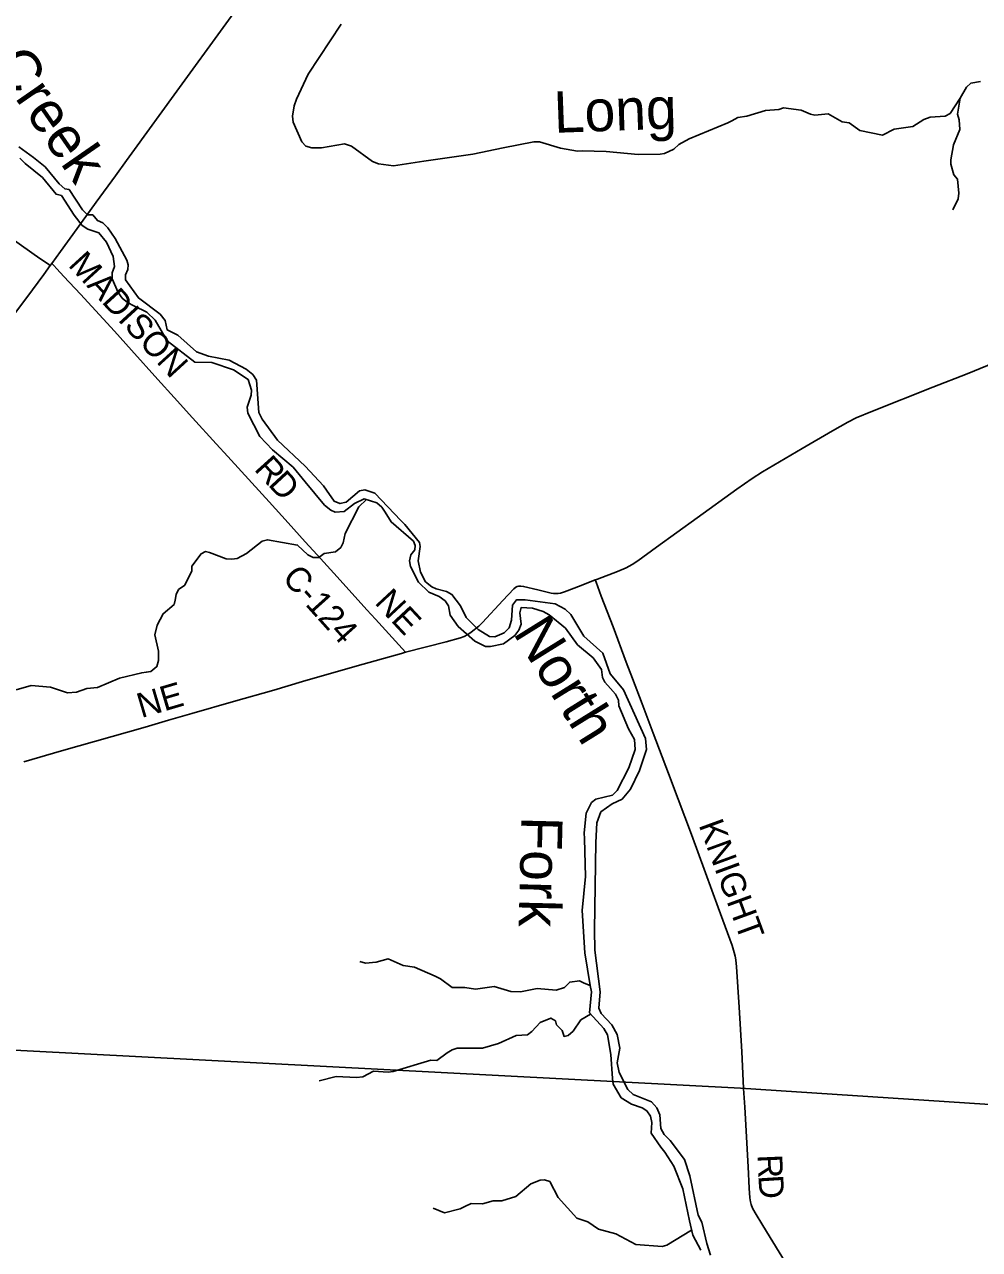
# Model space of a CAD drawing. Extents: x -51392 to 1635000, y 156707 to 696232.
# Drawn here: x 168915 to 180473, y 515913 to 530739 of the extents above; entities that cross this region are included whole.
import ezdxf

# ---------------------------------------------------------------- set-up
doc = ezdxf.new("R2010")
doc.units = 0
for name, color, linetype in [('GM_X_County_Road', 7, 'Continuous'), ('GM_X_County_Road_Text', 7, 'Continuous'), ('GM_X_Major_River', 7, 'Continuous'), ('GM_X_Major_River_Text', 7, 'Continuous'), ('GM_X_Minor_River', 7, 'Continuous'), ('GM_X_Minor_River_Text', 7, 'Continuous'), ('GM_X_Township', 7, 'Continuous'), ('GM_X_Township_Road', 7, 'Continuous'), ('GM_X_Township_Road_Text', 7, 'Continuous'), ('GM_X_US_Route', 7, 'Continuous')]:
    doc.layers.add(name, color=color, linetype=linetype)

msp = doc.modelspace()

# ---------------------------------------------------------------- linework, layer by layer
at = {"layer": 'GM_X_County_Road'}
for points in [[(167287, 529285), (167296, 529278), (167614, 529025), (167969, 528741), (168202, 528558), (168356, 528437), (168505, 528327), (168680, 528204), (168878, 528064), (169102, 527908), (169195, 527844), (169227, 527821)], [(173528, 523141), (173163, 523542), (173057, 523656), (172808, 523932), (172658, 524099), (172457, 524321), (172313, 524478), (172106, 524707), (171877, 524961), (171665, 525193), (171378, 525509), (171234, 525665), (170950, 525979), (170728, 526226), (170530, 526444), (170212, 526797), (170003, 527029), (169594, 527473), (169393, 527690), (169308, 527783), (169270, 527821), (169245, 527845)]]:
    msp.add_lwpolyline(points, dxfattribs=at)
at = {"layer": 'GM_X_Major_River'}
for points in [[(175686, 523337), (175528, 523598), (175458, 523662), (175337, 523726), (174976, 523777), (174868, 523775), (174820, 523711), (174810, 523530), (174782, 523438), (174719, 523376), (174607, 523328), (174541, 523330), (174406, 523416), (174262, 523560), (174194, 523703), (174088, 523841), (174024, 523877), (173897, 523910), (173845, 523932), (173769, 523994), (173707, 524110), (173679, 524247), (173705, 524419), (173695, 524469), (173519, 524686), (173470, 524736), (173156, 525067), (173033, 525106), (172971, 525094), (172807, 524959), (172733, 524941), (172662, 524969), (172570, 525102), (172536, 525156), (172314, 525393), (171979, 525708), (171790, 525963), (171752, 526043), (171724, 526434), (171678, 526502), (171600, 526569), (171392, 526675), (171141, 526723), (170997, 526778), (170770, 526978), (170644, 527043), (170618, 527157), (170556, 527231), (170295, 527430), (170139, 527647), (170137, 527709), (170165, 527773), (170169, 527829), (170155, 527885), (170012, 528150), (169924, 528277), (169862, 528337), (169798, 528365), (169742, 528435), (169678, 528435), (169618, 528495), (169455, 528740), (169405, 528748), (169337, 528810), (169165, 529015), (169026, 529129), (168848, 529260)], [(168858, 529120), (168924, 529055), (169134, 528885), (169297, 528684), (169363, 528670), (169515, 528431), (169613, 528307), (169680, 528261), (169754, 528238), (169816, 528216), (169906, 528106), (169990, 527929), (170004, 527809), (169976, 527735), (169976, 527661), (170048, 527496), (170096, 527428), (170161, 527374), (170237, 527332), (170397, 527257), (170497, 527159), (170644, 526912), (170978, 526653), (171183, 526647), (171444, 526561), (171624, 526442), (171664, 526314), (171660, 526252), (171612, 526107), (171620, 526033), (171762, 525754), (171917, 525592), (172167, 525381), (172311, 525204), (172548, 524923), (172622, 524861), (172676, 524837), (172785, 524845), (172909, 524943), (173025, 524999), (173178, 524951), (173240, 524895), (173280, 524837), (173352, 524718), (173625, 524485), (173645, 524431), (173641, 524381), (173589, 524319), (173575, 524249), (173587, 524177), (173683, 523988), (173809, 523868), (173935, 523817), (174006, 523763), (174048, 523701), (174068, 523591), (174164, 523452), (174366, 523277), (174495, 523211), (174555, 523209), (174711, 523241), (174848, 523343), (174900, 523410), (174926, 523482), (174910, 523620), (174928, 523684), (175062, 523674), (175193, 523634)], [(175193, 523634), (175267, 523592), (175461, 523431), (175610, 523229), (175796, 523072), (175898, 522932), (175912, 522837), (175940, 522777), (176009, 522701), (176069, 522633), (176103, 522562), (176109, 522492), (176227, 522213), (176297, 522087), (176307, 521965), (176229, 521742), (176088, 521467), (176030, 521413), (175830, 521361), (175779, 521321), (175713, 521193), (175687, 520954), (175691, 520882), (175705, 520426), (175666, 520017), (175698, 519504), (175760, 519106), (175777, 519031)], [(175883, 519032), (175817, 519536), (175813, 519780), (175831, 520837), (175843, 521078), (175890, 521209), (176028, 521307), (176148, 521363), (176251, 521483), (176357, 521708), (176377, 521772), (176442, 521962), (176432, 522097), (176163, 522687), (176107, 522755), (176005, 522879), (175915, 523128), (175686, 523337)], [(175777, 519031), (175754, 518776), (175927, 518586), (175971, 518511), (176011, 518273), (176031, 517982), (176041, 517912), (176137, 517750), (176261, 517672), (176389, 517627), (176447, 517589), (176493, 517525), (176507, 517451), (176501, 517321), (176617, 517152), (176665, 517092), (176775, 516922), (176883, 516645), (176964, 516260), (177002, 516086), (177102, 515905)], [(177218, 515845), (177174, 515987), (177111, 516243), (177070, 516329), (176967, 516805), (176901, 517002), (176731, 517230), (176657, 517304), (176617, 517377), (176605, 517543), (176567, 517629), (176503, 517699), (176281, 517788), (176219, 517850), (176111, 518056), (176089, 518173), (176121, 518351), (176087, 518513), (176025, 518632), (175894, 518768), (175866, 518834), (175883, 519032)]]:
    msp.add_lwpolyline(points, dxfattribs=at)
at = {"layer": 'GM_X_Minor_River'}
for points in [[(180238, 529848), (180117, 529663), (180059, 529631), (179877, 529619), (179798, 529589), (179668, 529503), (179439, 529471), (179299, 529401), (179026, 529457), (178896, 529548), (178812, 529562), (178643, 529658), (178479, 529642), (178429, 529654), (178316, 529702), (178100, 529731), (178046, 529709), (177883, 529697), (177656, 529629), (177548, 529613), (177476, 529573), (177426, 529548), (176960, 529356), (176834, 529286), (176774, 529228), (176661, 529176), (176607, 529170), (176343, 529166), (175953, 529202), (175665, 529210), (175609, 529206), (175404, 529241), (175147, 529317), (175079, 529317), (174708, 529245), (174341, 529171), (173747, 529085), (173382, 529029), (173200, 529051), (173128, 529081), (172871, 529268), (172787, 529294), (172510, 529246), (172392, 529244), (172319, 529266), (172271, 529320), (172167, 529555), (172159, 529631), (172181, 529756), (172207, 529834), (172348, 530137), (172747, 530741)], [(180484, 530050), (180368, 530028), (180314, 529982), (180238, 529848), (180207, 529653), (180229, 529583), (180237, 529467), (180157, 529284), (180125, 529100), (180125, 529047), (180163, 528921), (180207, 528867), (180225, 528696), (180213, 528630), (180151, 528496)], [(173055, 524990), (172963, 524899), (172795, 524578), (172772, 524466), (172742, 524408), (172678, 524358), (172544, 524338), (172478, 524289), (172409, 524289), (172345, 524320), (172221, 524438), (171858, 524502), (171792, 524484), (171603, 524338), (171491, 524276), (171425, 524268), (171356, 524270), (171156, 524350), (171106, 524360), (171052, 524334), (170941, 524182), (170939, 524126), (170855, 523951), (170779, 523899), (170749, 523839), (170740, 523773), (170726, 523719), (170594, 523606), (170522, 523468), (170494, 523352), (170536, 523153), (170536, 523041), (170517, 522967), (170445, 522910), (170389, 522898), (170335, 522892), (170064, 522826), (169797, 522716), (169671, 522702), (169543, 522658), (169434, 522648), (169232, 522718), (168995, 522739), (168813, 522685)], [(172973, 519397), (173043, 519379), (173173, 519391), (173318, 519431), (173498, 519350), (173634, 519330), (173885, 519222), (173951, 519190), (174090, 519085), (174246, 519085), (174372, 519065), (174601, 519095), (174800, 519035), (174918, 519033), (175120, 519071), (175351, 519050), (175451, 519083), (175514, 519149), (175634, 519163), (175688, 519135), (175760, 519106)], [(175766, 518761), (175649, 518692), (175555, 518556), (175495, 518502), (175445, 518492), (175421, 518562), (175355, 518630), (175343, 518680), (175285, 518714), (175155, 518661), (175057, 518550), (175001, 518512), (174865, 518501), (174653, 518405), (174457, 518349), (174153, 518351), (174093, 518331), (174031, 518291), (173905, 518199), (173831, 518203), (173377, 518067), (173317, 518057), (173139, 518072), (173009, 518004), (172933, 517994), (172689, 518008), (172481, 517952)], [(176988, 516148), (176688, 515966), (176632, 515950), (176312, 515972), (176072, 516103), (175864, 516159), (175732, 516247), (175600, 516292), (175374, 516540), (175272, 516735), (175208, 516755), (175156, 516753), (175044, 516707), (174860, 516555), (174694, 516501), (174586, 516501), (174458, 516465), (174322, 516471), (174246, 516431), (174188, 516405), (174000, 516358), (173862, 516412)]]:
    msp.add_lwpolyline(points, dxfattribs=at)
at = {"layer": 'GM_X_Township'}
for points in [[(167692, 546175), (177006, 545575), (182001, 545258), (186228, 544990), (191470, 544658), (190603, 531017), (189983, 519189), (189871, 517055), (188911, 517117), (188608, 517138), (188239, 517168), (177580, 517864), (162392, 518660)], [(162392, 518660), (177580, 517864), (188239, 517168), (188608, 517138), (188911, 517117), (189871, 517055), (189823, 516133), (189395, 507976), (188717, 497545)]]:
    msp.add_lwpolyline(points, dxfattribs=at)
at = {"layer": 'GM_X_Township_Road'}
for points in [[(175823, 524016), (175850, 524026), (176093, 524117), (176198, 524163), (176271, 524202), (176340, 524247), (176565, 524411), (177057, 524767), (177535, 525113), (177723, 525244), (177847, 525323), (178327, 525607), (178695, 525822), (178880, 525927), (178982, 525977), (179179, 526060), (179910, 526350), (180322, 526512), (180974, 526778), (181443, 526974), (181639, 527053), (181666, 527064)], [(173528, 523141), (174017, 523268), (174191, 523314), (174238, 523331), (174281, 523355), (174322, 523383), (174412, 523455), (174460, 523500), (174703, 523766), (174838, 523909), (174863, 523928), (174877, 523935), (174892, 523939), (174907, 523942), (174923, 523942), (174955, 523937), (175129, 523895), (175289, 523858), (175318, 523853), (175338, 523851), (175372, 523852), (175404, 523858), (175452, 523873), (175651, 523950), (175823, 524016)], [(177619, 517863), (177609, 518044), (177597, 518305), (177563, 518847), (177534, 519335), (177524, 519417), (177516, 519461), (177505, 519508), (177478, 519592), (177309, 520053), (177159, 520472), (176988, 520936), (176827, 521363), (176708, 521674), (176525, 522162), (176391, 522518), (176274, 522822), (176198, 523022), (176038, 523450), (175896, 523819), (175832, 523990), (175823, 524016)], [(168908, 521815), (169365, 521947), (170374, 522236), (170658, 522318), (170941, 522400), (171445, 522545), (171934, 522684), (172281, 522785), (172943, 522975), (173479, 523127), (173528, 523141)], [(179810, 512968), (179787, 513007), (179568, 513372), (179424, 513611), (179297, 513821), (179060, 514214), (178899, 514480), (178679, 514845), (178398, 515306), (178168, 515684), (177852, 516202), (177758, 516355), (177727, 516413), (177708, 516458), (177700, 516490), (177693, 516538), (177686, 516653), (177675, 516915), (177633, 517634), (177619, 517863)]]:
    msp.add_lwpolyline(points, dxfattribs=at)
at = {"layer": 'GM_X_US_Route'}
for points in [[(170150, 529093), (170246, 529225), (170728, 529889), (171383, 530793), (171566, 531045), (172344, 532122), (172565, 532427), (172679, 532587), (172784, 532734), (173054, 533105), (173748, 534061), (173893, 534261), (174028, 534446), (174122, 534580), (175240, 536121), (175404, 536346), (175674, 536717), (175864, 536978)], [(168750, 527175), (169011, 527528), (169148, 527712), (169227, 527821), (169245, 527845), (169350, 527991), (169553, 528270), (169784, 528588), (170015, 528907), (170150, 529093)]]:
    msp.add_lwpolyline(points, dxfattribs=at)

# ---------------------------------------------------------------- texts
at = {"layer": 'GM_X_County_Road_Text'}
for s, rotation, p in [('MADISON', 312.4272, (169434, 527822)), ('R', 312.1504, (171684, 525352)), ('D', 312.9013, (171853, 525166)), ('C-124', 311.8777, (172022, 524032)), ('NE', 312.9842, (173142, 523735))]:
    msp.add_text(s, height=300, rotation=rotation, dxfattribs=at).set_placement(p)
at = {"layer": 'GM_X_Major_River_Text'}
for s, rotation, p in [('Creek', 304.7049, (168518, 530250)), ('North', 301.8516, (174821, 523375)), ('Fork', 268.5501, (174929, 521159))]:
    msp.add_text(s, height=500, rotation=rotation, dxfattribs=at).set_placement(p)
at = {"layer": 'GM_X_Minor_River_Text'}
msp.add_text('Long', height=500, rotation=2.0524, dxfattribs=at).set_placement((175329, 529427))
at = {"layer": 'GM_X_Township_Road_Text'}
for s, rotation, p in [('NE', 16.4158, (170329, 522343)), ('KNIGHT', 290.1083, (177072, 521052)), ('R', 272.4514, (177785, 517058)), ('D', 273.6108, (177796, 516806))]:
    msp.add_text(s, height=300, rotation=rotation, dxfattribs=at).set_placement(p)

doc.saveas('drawing.dxf')
